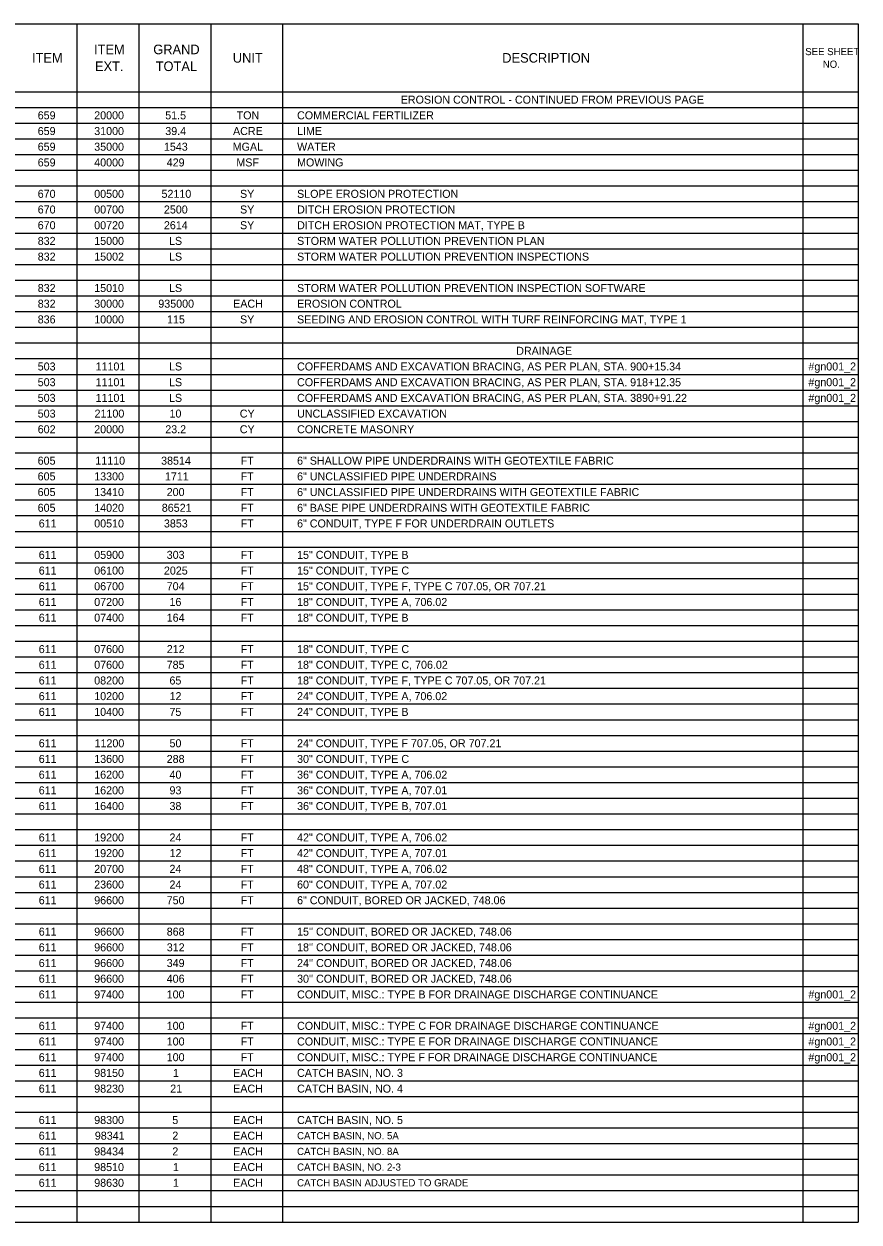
# Model space of a CAD drawing. Extents: x -542 to 295, y -281 to 32.
# Drawn here: x -525.79 to -511.19, y -40.54 to -19.59 of the extents above; entities that cross this region are included whole.
import ezdxf

# ---------------------------------------------------------------- set-up
doc = ezdxf.new("R2010")
doc.units = 0
doc.layers.add('SH_Data', color=7, linetype='Continuous')
doc.layers.add('SH_Text', color=7, linetype='Continuous')

msp = doc.modelspace()

# ---------------------------------------------------------------- linework, layer by layer
at = {"layer": 'SH_Data'}
for p, q in [((-541.706, -19.593), (-511.206, -19.593)), ((-524.87, -19.593), (-524.87, -40.543)), ((-523.785, -19.593), (-523.785, -40.543)), ((-522.529, -19.593), (-522.529, -40.543)), ((-521.273, -19.593), (-521.273, -40.543)), ((-512.174, -19.593), (-512.174, -40.543)), ((-511.206, -19.593), (-511.206, -40.543)), ((-541.706, -20.778), (-511.206, -20.778)), ((-541.706, -21.053), (-511.206, -21.053)), ((-541.706, -21.327), (-511.206, -21.327)), ((-541.706, -21.602), (-511.206, -21.602)), ((-541.706, -21.876), (-511.206, -21.876)), ((-541.706, -22.151), (-511.206, -22.151)), ((-541.706, -22.425), (-511.206, -22.425)), ((-541.706, -22.7), (-511.206, -22.7)), ((-541.706, -22.975), (-511.206, -22.975)), ((-541.706, -23.249), (-511.206, -23.249)), ((-541.706, -23.524), (-511.206, -23.524)), ((-541.706, -23.798), (-511.206, -23.798)), ((-541.706, -24.073), (-511.206, -24.073)), ((-541.706, -24.347), (-511.206, -24.347)), ((-541.706, -24.622), (-511.206, -24.622)), ((-541.706, -24.896), (-511.206, -24.896)), ((-541.706, -25.171), (-511.206, -25.171)), ((-541.706, -25.445), (-511.206, -25.445)), ((-541.706, -25.72), (-511.206, -25.72)), ((-541.706, -25.994), (-511.206, -25.994)), ((-541.706, -26.269), (-511.206, -26.269)), ((-541.706, -26.543), (-511.206, -26.543)), ((-541.706, -26.818), (-511.206, -26.818)), ((-541.706, -27.092), (-511.206, -27.092)), ((-541.706, -27.367), (-511.206, -27.367)), ((-541.706, -27.641), (-511.206, -27.641)), ((-541.706, -27.916), (-511.206, -27.916)), ((-541.706, -28.19), (-511.206, -28.19)), ((-541.706, -28.465), (-511.206, -28.465)), ((-541.706, -28.739), (-511.206, -28.739)), ((-541.706, -29.014), (-511.206, -29.014)), ((-541.706, -29.288), (-511.206, -29.288)), ((-541.706, -29.563), (-511.206, -29.563)), ((-541.706, -29.837), (-511.206, -29.837)), ((-541.706, -30.112), (-511.206, -30.112)), ((-541.706, -30.386), (-511.206, -30.386)), ((-541.706, -30.661), (-511.206, -30.661)), ((-541.706, -30.935), (-511.206, -30.935)), ((-541.706, -31.21), (-511.206, -31.21)), ((-541.706, -31.484), (-511.206, -31.484)), ((-541.706, -31.759), (-511.206, -31.759)), ((-541.706, -32.033), (-511.206, -32.033)), ((-541.706, -32.308), (-511.206, -32.308)), ((-541.706, -32.582), (-511.206, -32.582)), ((-541.706, -32.857), (-511.206, -32.857)), ((-541.706, -33.131), (-511.206, -33.131)), ((-541.706, -33.406), (-511.206, -33.406)), ((-541.706, -33.68), (-511.206, -33.68)), ((-541.706, -33.955), (-511.206, -33.955)), ((-541.706, -34.229), (-511.206, -34.229)), ((-541.706, -34.504), (-511.206, -34.504)), ((-541.706, -34.778), (-511.206, -34.778)), ((-541.706, -35.053), (-511.206, -35.053)), ((-541.706, -35.327), (-511.206, -35.327)), ((-541.706, -35.602), (-511.206, -35.602)), ((-541.706, -35.876), (-511.206, -35.876)), ((-541.706, -36.151), (-511.206, -36.151)), ((-541.706, -36.425), (-511.206, -36.425)), ((-541.706, -36.7), (-511.206, -36.7)), ((-541.706, -36.975), (-511.206, -36.975)), ((-541.706, -37.249), (-511.206, -37.249)), ((-541.706, -37.524), (-511.206, -37.524)), ((-541.706, -37.798), (-511.206, -37.798)), ((-541.706, -38.073), (-511.206, -38.073)), ((-541.706, -38.347), (-511.206, -38.347)), ((-541.706, -38.622), (-511.206, -38.622)), ((-541.706, -38.896), (-511.206, -38.896)), ((-541.706, -39.171), (-511.206, -39.171)), ((-541.706, -39.445), (-511.206, -39.445)), ((-541.706, -39.72), (-511.206, -39.72)), ((-541.706, -39.994), (-511.206, -39.994)), ((-541.706, -40.269), (-511.206, -40.269)), ((-541.706, -40.543), (-511.206, -40.543))]:
    msp.add_line(p, q, dxfattribs=at)

# ---------------------------------------------------------------- texts
at = {"layer": 'SH_Text'}
for s, height, p in [('ITEM', 0.168, (-525.654, -20.269)), ('ITEM', 0.168, (-524.569, -20.122)), ('GRAND ', 0.168, (-523.533, -20.122)), ('UNIT', 0.168, (-522.142, -20.269)), ('DESCRIPTION', 0.168, (-517.43, -20.269)), ('SEE SHEET ', 0.126, (-512.131, -20.138)), ('EXT.', 0.168, (-524.552, -20.416)), ('TOTAL', 0.168, (-523.491, -20.416)), ('NO.', 0.126, (-511.824, -20.359)), ('EROSION CONTROL - CONTINUED FROM PREVIOUS PAGE', 0.14, (-519.205, -20.986)), ('659', 0.14, (-525.554, -21.26)), ('20000', 0.14, (-524.566, -21.26)), ('51.5', 0.14, (-523.324, -21.26)), ('TON', 0.14, (-522.075, -21.26)), ('COMMERCIAL FERTILIZER', 0.14, (-521.018, -21.26)), ('659', 0.14, (-525.554, -21.535)), ('31000', 0.14, (-524.566, -21.535)), ('39.4', 0.14, (-523.323, -21.535)), ('ACRE', 0.14, (-522.138, -21.535)), ('LIME', 0.14, (-521.018, -21.535)), ('659', 0.14, (-525.554, -21.809)), ('35000', 0.14, (-524.566, -21.809)), ('1543', 0.14, (-523.347, -21.809)), ('MGAL', 0.14, (-522.144, -21.809)), ('WATER', 0.14, (-521.018, -21.809)), ('659', 0.14, (-525.554, -22.084)), ('40000', 0.14, (-524.566, -22.084)), ('429', 0.14, (-523.298, -22.084)), ('MSF', 0.14, (-522.08, -22.084)), ('MOWING', 0.14, (-521.018, -22.084)), ('670', 0.14, (-525.554, -22.633)), ('00500', 0.14, (-524.566, -22.633)), ('52110', 0.14, (-523.389, -22.633)), ('SY', 0.14, (-522.016, -22.633)), ('SLOPE EROSION PROTECTION', 0.14, (-521.018, -22.633)), ('670', 0.14, (-525.554, -22.907)), ('00700', 0.14, (-524.566, -22.907)), ('2500', 0.14, (-523.347, -22.907)), ('SY', 0.14, (-522.016, -22.907)), ('DITCH EROSION PROTECTION', 0.14, (-521.018, -22.907)), ('670', 0.14, (-525.554, -23.182)), ('00720', 0.14, (-524.566, -23.182)), ('2614', 0.14, (-523.347, -23.182)), ('SY', 0.14, (-522.016, -23.182)), ('DITCH EROSION PROTECTION MAT, TYPE B', 0.14, (-521.018, -23.182)), ('832', 0.14, (-525.554, -23.456)), ('15000', 0.14, (-524.566, -23.456)), ('LS', 0.14, (-523.258, -23.456)), ('STORM WATER POLLUTION PREVENTION PLAN', 0.14, (-521.018, -23.456)), ('832', 0.14, (-525.554, -23.731)), ('15002', 0.14, (-524.566, -23.731)), ('LS', 0.14, (-523.258, -23.731)), ('STORM WATER POLLUTION PREVENTION INSPECTIONS', 0.14, (-521.018, -23.731)), ('832', 0.14, (-525.554, -24.28)), ('15010', 0.14, (-524.566, -24.28)), ('LS', 0.14, (-523.258, -24.28)), ('STORM WATER POLLUTION PREVENTION INSPECTION SOFTWARE', 0.14, (-521.018, -24.28)), ('832', 0.14, (-525.554, -24.554)), ('30000', 0.14, (-524.566, -24.554)), ('935000', 0.14, (-523.445, -24.554)), ('EACH', 0.14, (-522.136, -24.554)), ('EROSION CONTROL', 0.14, (-521.018, -24.554)), ('836', 0.14, (-525.554, -24.829)), ('10000', 0.14, (-524.566, -24.829)), ('115', 0.14, (-523.292, -24.829)), ('SY', 0.14, (-522.016, -24.829)), ('SEEDING AND EROSION CONTROL WITH TURF REINFORCING MAT, TYPE 1', 0.14, (-521.018, -24.829)), ('DRAINAGE', 0.14, (-517.185, -25.378)), ('503', 0.14, (-525.554, -25.652)), ('11101', 0.14, (-524.542, -25.652)), ('LS', 0.14, (-523.258, -25.652)), ('COFFERDAMS AND EXCAVATION BRACING, AS PER PLAN, STA. 900+15.34', 0.14, (-521.018, -25.652)), ('#gn001_2', 0.14, (-512.075, -25.652)), ('503', 0.14, (-525.554, -25.927)), ('11101', 0.14, (-524.542, -25.927)), ('LS', 0.14, (-523.258, -25.927)), ('COFFERDAMS AND EXCAVATION BRACING, AS PER PLAN, STA. 918+12.35', 0.14, (-521.018, -25.927)), ('#gn001_2', 0.14, (-512.075, -25.927)), ('503', 0.14, (-525.554, -26.201)), ('11101', 0.14, (-524.542, -26.201)), ('LS', 0.14, (-523.258, -26.201)), ('COFFERDAMS AND EXCAVATION BRACING, AS PER PLAN, STA. 3890+91.22', 0.14, (-521.018, -26.201)), ('#gn001_2', 0.14, (-512.075, -26.201)), ('503', 0.14, (-525.554, -26.476)), ('21100', 0.14, (-524.56, -26.476)), ('10', 0.14, (-523.249, -26.476)), ('CY', 0.14, (-522.02, -26.476)), ('UNCLASSIFIED EXCAVATION', 0.14, (-521.018, -26.476)), ('602', 0.14, (-525.554, -26.75)), ('20000', 0.14, (-524.566, -26.75)), ('23.2', 0.14, (-523.323, -26.75)), ('CY', 0.14, (-522.02, -26.75)), ('CONCRETE MASONRY', 0.14, (-521.018, -26.75)), ('605', 0.14, (-525.555, -27.299)), ('11110', 0.14, (-524.547, -27.299)), ('38514', 0.14, (-523.396, -27.299)), ('FT', 0.14, (-522.005, -27.299)), ('6" SHALLOW PIPE UNDERDRAINS WITH GEOTEXTILE FABRIC', 0.14, (-521.018, -27.299)), ('605', 0.14, (-525.555, -27.574)), ('13300', 0.14, (-524.566, -27.574)), ('1711', 0.14, (-523.329, -27.574)), ('FT', 0.14, (-522.005, -27.574)), ('6" UNCLASSIFIED PIPE UNDERDRAINS', 0.14, (-521.018, -27.574)), ('605', 0.14, (-525.555, -27.848)), ('13410', 0.14, (-524.566, -27.848)), ('200', 0.14, (-523.298, -27.848)), ('FT', 0.14, (-522.005, -27.848)), ('6" UNCLASSIFIED PIPE UNDERDRAINS WITH GEOTEXTILE FABRIC', 0.14, (-521.018, -27.848)), ('605', 0.14, (-525.555, -28.123)), ('14020', 0.14, (-524.566, -28.123)), ('86521', 0.14, (-523.384, -28.123)), ('FT', 0.14, (-522.005, -28.123)), ('6" BASE PIPE UNDERDRAINS WITH GEOTEXTILE FABRIC', 0.14, (-521.018, -28.123)), ('611', 0.14, (-525.536, -28.397)), ('00510', 0.14, (-524.566, -28.397)), ('3853', 0.14, (-523.347, -28.397)), ('FT', 0.14, (-522.005, -28.397)), ('6" CONDUIT, TYPE F FOR UNDERDRAIN OUTLETS', 0.14, (-521.018, -28.397)), ('611', 0.14, (-525.536, -28.946)), ('05900', 0.14, (-524.566, -28.946)), ('303', 0.14, (-523.298, -28.946)), ('FT', 0.14, (-522.005, -28.946)), ('15" CONDUIT, TYPE B', 0.14, (-521.018, -28.946)), ('611', 0.14, (-525.536, -29.221)), ('06100', 0.14, (-524.566, -29.221)), ('2025', 0.14, (-523.347, -29.221)), ('FT', 0.14, (-522.005, -29.221)), ('15" CONDUIT, TYPE C', 0.14, (-521.018, -29.221)), ('611', 0.14, (-525.536, -29.495)), ('06700', 0.14, (-524.566, -29.495)), ('704', 0.14, (-523.298, -29.495)), ('FT', 0.14, (-522.005, -29.495)), ('15" CONDUIT, TYPE F, TYPE C 707.05, OR 707.21', 0.14, (-521.018, -29.495)), ('611', 0.14, (-525.536, -29.77)), ('07200', 0.14, (-524.566, -29.77)), ('16', 0.14, (-523.249, -29.77)), ('FT', 0.14, (-522.005, -29.77)), ('18" CONDUIT, TYPE A, 706.02', 0.14, (-521.018, -29.77)), ('611', 0.14, (-525.536, -30.045)), ('07400', 0.14, (-524.566, -30.045)), ('164', 0.14, (-523.298, -30.045)), ('FT', 0.14, (-522.005, -30.045)), ('18" CONDUIT, TYPE B', 0.14, (-521.018, -30.045)), ('611', 0.14, (-525.536, -30.594)), ('07600', 0.14, (-524.566, -30.594)), ('212', 0.14, (-523.297, -30.594)), ('FT', 0.14, (-522.005, -30.594)), ('18" CONDUIT, TYPE C', 0.14, (-521.018, -30.594)), ('611', 0.14, (-525.536, -30.868)), ('07600', 0.14, (-524.566, -30.868)), ('785', 0.14, (-523.299, -30.868)), ('FT', 0.14, (-522.005, -30.868)), ('18" CONDUIT, TYPE C, 706.02', 0.14, (-521.018, -30.868)), ('611', 0.14, (-525.536, -31.143)), ('08200', 0.14, (-524.566, -31.143)), ('65', 0.14, (-523.25, -31.143)), ('FT', 0.14, (-522.005, -31.143)), ('18" CONDUIT, TYPE F, TYPE C 707.05, OR 707.21', 0.14, (-521.018, -31.143)), ('611', 0.14, (-525.536, -31.417)), ('10200', 0.14, (-524.566, -31.417)), ('12', 0.14, (-523.248, -31.417)), ('FT', 0.14, (-522.005, -31.417)), ('24" CONDUIT, TYPE A, 706.02', 0.14, (-521.018, -31.417)), ('611', 0.14, (-525.536, -31.692)), ('10400', 0.14, (-524.566, -31.692)), ('75', 0.14, (-523.25, -31.692)), ('FT', 0.14, (-522.005, -31.692)), ('24" CONDUIT, TYPE B', 0.14, (-521.018, -31.692)), ('611', 0.14, (-525.536, -32.241)), ('11200', 0.14, (-524.56, -32.241)), ('50', 0.14, (-523.249, -32.241)), ('FT', 0.14, (-522.005, -32.241)), ('24" CONDUIT, TYPE F 707.05, OR 707.21', 0.14, (-521.018, -32.241)), ('611', 0.14, (-525.536, -32.515)), ('13600', 0.14, (-524.566, -32.515)), ('288', 0.14, (-523.298, -32.515)), ('FT', 0.14, (-522.005, -32.515)), ('30" CONDUIT, TYPE C', 0.14, (-521.018, -32.515)), ('611', 0.14, (-525.536, -32.79)), ('16200', 0.14, (-524.566, -32.79)), ('40', 0.14, (-523.249, -32.79)), ('FT', 0.14, (-522.005, -32.79)), ('36" CONDUIT, TYPE A, 706.02', 0.14, (-521.018, -32.79)), ('611', 0.14, (-525.536, -33.064)), ('16200', 0.14, (-524.566, -33.064)), ('93', 0.14, (-523.249, -33.064)), ('FT', 0.14, (-522.005, -33.064)), ('36" CONDUIT, TYPE A, 707.01', 0.14, (-521.018, -33.064)), ('611', 0.14, (-525.536, -33.339)), ('16400', 0.14, (-524.566, -33.339)), ('38', 0.14, (-523.249, -33.339)), ('FT', 0.14, (-522.005, -33.339)), ('36" CONDUIT, TYPE B, 707.01', 0.14, (-521.018, -33.339)), ('611', 0.14, (-525.536, -33.888)), ('19200', 0.14, (-524.566, -33.888)), ('24', 0.14, (-523.249, -33.888)), ('FT', 0.14, (-522.005, -33.888)), ('42" CONDUIT, TYPE A, 706.02', 0.14, (-521.018, -33.888)), ('611', 0.14, (-525.536, -34.162)), ('19200', 0.14, (-524.566, -34.162)), ('12', 0.14, (-523.248, -34.162)), ('FT', 0.14, (-522.005, -34.162)), ('42" CONDUIT, TYPE A, 707.01', 0.14, (-521.018, -34.162)), ('611', 0.14, (-525.536, -34.437)), ('20700', 0.14, (-524.566, -34.437)), ('24', 0.14, (-523.249, -34.437)), ('FT', 0.14, (-522.005, -34.437)), ('48" CONDUIT, TYPE A, 706.02', 0.14, (-521.018, -34.437)), ('611', 0.14, (-525.536, -34.711)), ('23600', 0.14, (-524.566, -34.711)), ('24', 0.14, (-523.249, -34.711)), ('FT', 0.14, (-522.005, -34.711)), ('60" CONDUIT, TYPE A, 707.02', 0.14, (-521.018, -34.711)), ('611', 0.14, (-525.536, -34.986)), ('96600', 0.14, (-524.566, -34.986)), ('750', 0.14, (-523.298, -34.986)), ('FT', 0.14, (-522.005, -34.986)), ('6" CONDUIT, BORED OR JACKED, 748.06', 0.14, (-521.018, -34.986)), ('611', 0.14, (-525.536, -35.535)), ('96600', 0.14, (-524.566, -35.535)), ('868', 0.14, (-523.298, -35.535)), ('FT', 0.14, (-522.005, -35.535)), ("15'' CONDUIT, BORED OR JACKED, 748.06", 0.14, (-521.018, -35.535)), ('611', 0.14, (-525.536, -35.809)), ('96600', 0.14, (-524.566, -35.809)), ('312', 0.14, (-523.297, -35.809)), ('FT', 0.14, (-522.005, -35.809)), ("18'' CONDUIT, BORED OR JACKED, 748.06", 0.14, (-521.018, -35.809)), ('611', 0.14, (-525.536, -36.084)), ('96600', 0.14, (-524.566, -36.084)), ('349', 0.14, (-523.298, -36.084)), ('FT', 0.14, (-522.005, -36.084)), ("24'' CONDUIT, BORED OR JACKED, 748.06", 0.14, (-521.018, -36.084)), ('611', 0.14, (-525.536, -36.358)), ('96600', 0.14, (-524.566, -36.358)), ('406', 0.14, (-523.298, -36.358)), ('FT', 0.14, (-522.005, -36.358)), ("30'' CONDUIT, BORED OR JACKED, 748.06", 0.14, (-521.018, -36.358)), ('611', 0.14, (-525.536, -36.633)), ('97400', 0.14, (-524.566, -36.633)), ('100', 0.14, (-523.298, -36.633)), ('FT', 0.14, (-522.005, -36.633)), ('CONDUIT, MISC.: TYPE B FOR DRAINAGE DISCHARGE CONTINUANCE', 0.14, (-521.018, -36.633)), ('#gn001_2', 0.14, (-512.075, -36.633)), ('611', 0.14, (-525.536, -37.182)), ('97400', 0.14, (-524.566, -37.182)), ('100', 0.14, (-523.298, -37.182)), ('FT', 0.14, (-522.005, -37.182)), ('CONDUIT, MISC.: TYPE C FOR DRAINAGE DISCHARGE CONTINUANCE', 0.14, (-521.018, -37.182)), ('#gn001_2', 0.14, (-512.075, -37.182)), ('611', 0.14, (-525.536, -37.456)), ('97400', 0.14, (-524.566, -37.456)), ('100', 0.14, (-523.298, -37.456)), ('FT', 0.14, (-522.005, -37.456)), ('CONDUIT, MISC.: TYPE E FOR DRAINAGE DISCHARGE CONTINUANCE', 0.14, (-521.018, -37.456)), ('#gn001_2', 0.14, (-512.075, -37.456)), ('611', 0.14, (-525.536, -37.731)), ('97400', 0.14, (-524.566, -37.731)), ('100', 0.14, (-523.298, -37.731)), ('FT', 0.14, (-522.005, -37.731)), ('CONDUIT, MISC.: TYPE F FOR DRAINAGE DISCHARGE CONTINUANCE', 0.14, (-521.018, -37.731)), ('#gn001_2', 0.14, (-512.075, -37.731)), ('611', 0.14, (-525.536, -38.005)), ('98150', 0.14, (-524.566, -38.005)), ('1', 0.14, (-523.188, -38.005)), ('EACH', 0.14, (-522.136, -38.005)), ('CATCH BASIN, NO. 3', 0.14, (-521.018, -38.005)), ('611', 0.14, (-525.536, -38.28)), ('98230', 0.14, (-524.566, -38.28)), ('21', 0.14, (-523.237, -38.28)), ('EACH', 0.14, (-522.136, -38.28)), ('CATCH BASIN, NO. 4', 0.14, (-521.018, -38.28)), ('611', 0.14, (-525.536, -38.829)), ('98300', 0.14, (-524.566, -38.829)), ('5', 0.14, (-523.201, -38.829)), ('EACH', 0.14, (-522.136, -38.829)), ('CATCH BASIN, NO. 5', 0.14, (-521.018, -38.829)), ('611', 0.14, (-525.536, -39.103)), ('98341', 0.14, (-524.555, -39.103)), ('2', 0.14, (-523.2, -39.103)), ('EACH', 0.14, (-522.136, -39.103)), ('CATCH BASIN, NO. 5A', 0.126, (-521.018, -39.096)), ('611', 0.14, (-525.536, -39.378)), ('98434', 0.14, (-524.566, -39.378)), ('2', 0.14, (-523.2, -39.378)), ('EACH', 0.14, (-522.136, -39.378)), ('CATCH BASIN, NO. 8A', 0.126, (-521.018, -39.371)), ('611', 0.14, (-525.536, -39.652)), ('98510', 0.14, (-524.566, -39.652)), ('1', 0.14, (-523.188, -39.652)), ('EACH', 0.14, (-522.136, -39.652)), ('CATCH BASIN, NO. 2-3', 0.126, (-521.018, -39.645)), ('611', 0.14, (-525.536, -39.927)), ('98630', 0.14, (-524.566, -39.927)), ('1', 0.14, (-523.188, -39.927)), ('EACH', 0.14, (-522.136, -39.927)), ('CATCH BASIN ADJUSTED TO GRADE', 0.126, (-521.018, -39.92))]:
    msp.add_text(s, height=height, dxfattribs=at).set_placement(p)

doc.saveas('drawing.dxf')
